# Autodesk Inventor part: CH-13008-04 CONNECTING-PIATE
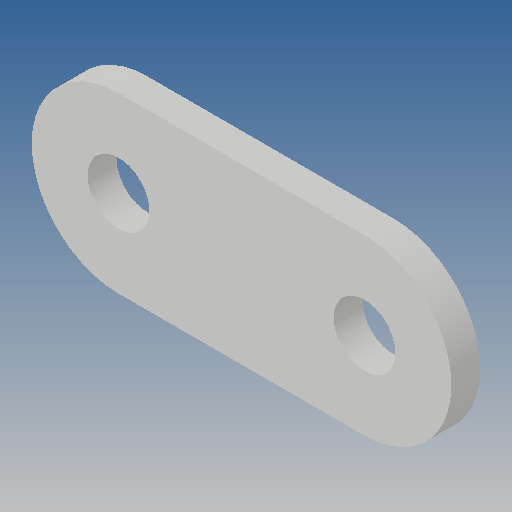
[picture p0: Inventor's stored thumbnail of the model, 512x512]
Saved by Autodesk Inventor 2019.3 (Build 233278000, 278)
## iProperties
Created: 2012-09
Part Number: CH-13008-04 CONNECTING-PIATE
Material: Ogólny
Document SubType Name: Modeling
Designer: CADENGINEERING4
Density: 1 g/cm^3
Appearance: Domyślna
Author: CADENGINEERING4
Revision Number: ÈÎºÎ
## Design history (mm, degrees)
feature "À­Éì1"
node "Bryła1"
